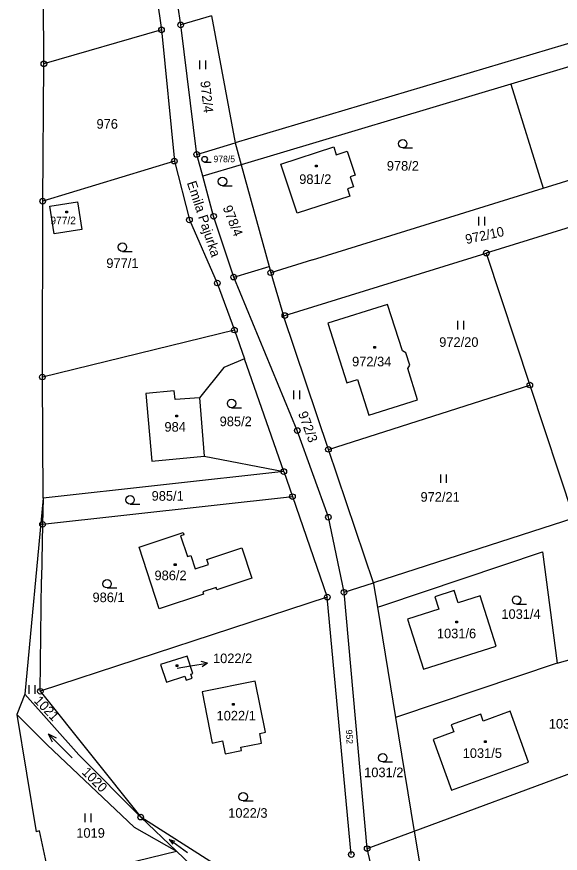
# Model space of a CAD drawing. Extents: x -468021 to -466942, y -1130484 to -1128584.
# Drawn here: x -467170.8 to -467074.6, y -1129387.9 to -1129239.8 of the extents above; entities that cross this region are included whole.
import ezdxf

# ---------------------------------------------------------------- set-up
doc = ezdxf.new("R2010")
doc.units = 0
doc.layers.add('DKM', color=7, linetype='Continuous')

msp = doc.modelspace()

# ---------------------------------------------------------------- linework, layer by layer
at = {"layer": 'DKM'}
for p, q in [((-467148.33, -1129219.55), (-467145.18, -1129242.09)), ((-467166.01, -1129248.11), (-467166.19, -1129224.44)), ((-467141.78, -1129241.21), (-467142.45, -1129236.44)), ((-467048.81, -1129237.23), (-467132.13, -1129262.11)), ((-467136.35, -1129239.61), (-467141.78, -1129241.21)), ((-467136.35, -1129239.61), (-467132.13, -1129262.11)), ((-467145.18, -1129242.09), (-467166.01, -1129248.11)), ((-467145.18, -1129242.09), (-467142.9, -1129265.33)), ((-467138.94, -1129264.14), (-467141.78, -1129241.21)), ((-467047.69, -1129241.07), (-467083.32, -1129251.71)), ((-467166.22, -1129272.43), (-467166.01, -1129248.11)), ((-467138.41, -1129249.04), (-467138.41, -1129247.54)), ((-467137.41, -1129247.54), (-467137.41, -1129249.04)), ((-467083.32, -1129251.71), (-467131.07, -1129265.96)), ((-467083.32, -1129251.71), (-467077.6, -1129270.12)), ((-467138.94, -1129264.14), (-467132.13, -1129262.11)), ((-467132.13, -1129262.11), (-467131.07, -1129265.96)), ((-467124.04, -1129265.86), (-467114.69, -1129262.77)), ((-467114.69, -1129262.77), (-467114.24, -1129264.19)), ((-467102.46, -1129262.99), (-467100.71, -1129262.99)), ((-467137.89, -1129268), (-467138.94, -1129264.14)), ((-467114.24, -1129264.19), (-467112.29, -1129263.55)), ((-467112.29, -1129263.55), (-467110.87, -1129267.83)), ((-467142.9, -1129265.33), (-467166.22, -1129272.43)), ((-467142.9, -1129265.33), (-467140.24, -1129275.75)), ((-467131.07, -1129265.96), (-467137.89, -1129268)), ((-467137.54, -1129265.49), (-467136.37, -1129265.49)), ((-467131.07, -1129265.96), (-467126.13, -1129284.01)), ((-467121.13, -1129274.57), (-467124.04, -1129265.86)), ((-467117.89, -1129266.06), (-467117.59, -1129266.06)), ((-467117.89, -1129266.36), (-467117.89, -1129266.06)), ((-467117.59, -1129266.06), (-467117.59, -1129266.36)), ((-467117.59, -1129266.36), (-467117.89, -1129266.36)), ((-467077.6, -1129270.12), (-467069.36, -1129267.56)), ((-467135.95, -1129275.1), (-467137.89, -1129268)), ((-467110.87, -1129267.83), (-467111.78, -1129268.12)), ((-467111.78, -1129268.12), (-467111.2, -1129269.88)), ((-467134.39, -1129269.68), (-467132.64, -1129269.68)), ((-467118.43, -1129282.79), (-467077.6, -1129270.12)), ((-467111.2, -1129269.88), (-467112.24, -1129270.23)), ((-467112.24, -1129270.23), (-467111.82, -1129271.51)), ((-467111.82, -1129271.51), (-467121.13, -1129274.57)), ((-467166.28, -1129303.56), (-467166.22, -1129272.43)), ((-467162.12, -1129274.18), (-467161.82, -1129274.18)), ((-467162.12, -1129274.48), (-467162.12, -1129274.18)), ((-467161.82, -1129274.48), (-467162.12, -1129274.48)), ((-467161.82, -1129274.18), (-467161.82, -1129274.48)), ((-467140.24, -1129275.75), (-467135.3, -1129286.92)), ((-467132.39, -1129285.86), (-467135.95, -1129275.1)), ((-467088.99, -1129276.7), (-467088.99, -1129275.2)), ((-467087.99, -1129275.2), (-467087.99, -1129276.7)), ((-467069.03, -1129275.85), (-467087.66, -1129281.62)), ((-467152.11, -1129281.31), (-467150.36, -1129281.31)), ((-467123.34, -1129292.67), (-467087.66, -1129281.62)), ((-467087.66, -1129281.62), (-467079.95, -1129304.98)), ((-467118.43, -1129282.79), (-467125.84, -1129285.08)), ((-467132.39, -1129285.86), (-467126.13, -1129284.01)), ((-467126.13, -1129284.01), (-467125.84, -1129285.08)), ((-467125.84, -1129285.08), (-467123.57, -1129292.74)), ((-467121.13, -1129313.03), (-467132.39, -1129285.86)), ((-467135.3, -1129286.92), (-467132.27, -1129295.24)), ((-467105.15, -1129290.73), (-467115.7, -1129294.04)), ((-467102.53, -1129298.94), (-467105.15, -1129290.73)), ((-467123.57, -1129292.74), (-467123.34, -1129292.67)), ((-467115.61, -1129316.37), (-467123.57, -1129292.74)), ((-467115.7, -1129294.04), (-467112.37, -1129304.59)), ((-467092.68, -1129295.12), (-467092.68, -1129293.62)), ((-467091.68, -1129293.62), (-467091.68, -1129295.12)), ((-467132.27, -1129295.24), (-467166.28, -1129303.56)), ((-467132.27, -1129295.24), (-467130.49, -1129300.34)), ((-467107.58, -1129298.14), (-467107.28, -1129298.14)), ((-467107.58, -1129298.44), (-467107.58, -1129298.14)), ((-467107.28, -1129298.44), (-467107.58, -1129298.44)), ((-467107.28, -1129298.14), (-467107.28, -1129298.44)), ((-467101.9, -1129299.25), (-467102.53, -1129298.94)), ((-467101.21, -1129301.44), (-467101.9, -1129299.25)), ((-467130.49, -1129300.34), (-467134.12, -1129301.86)), ((-467123.53, -1129320.29), (-467130.49, -1129300.34)), ((-467101.55, -1129302.05), (-467101.21, -1129301.44)), ((-467134.12, -1129301.86), (-467138.44, -1129307.25)), ((-467099.83, -1129307.62), (-467101.55, -1129302.05)), ((-467166.15, -1129325.02), (-467166.28, -1129303.56)), ((-467112.37, -1129304.59), (-467110.49, -1129304)), ((-467110.49, -1129304), (-467108.49, -1129310.3)), ((-467142.91, -1129306.01), (-467147.94, -1129306.45)), ((-467142.74, -1129307.54), (-467142.91, -1129306.01)), ((-467121.77, -1129307.47), (-467121.77, -1129305.97)), ((-467120.77, -1129305.97), (-467120.77, -1129307.47)), ((-467115.61, -1129316.37), (-467079.95, -1129304.98)), ((-467079.95, -1129304.98), (-467072.24, -1129328.35)), ((-467147.94, -1129306.45), (-467146.89, -1129318.46)), ((-467138.44, -1129307.25), (-467142.74, -1129307.54)), ((-467138.44, -1129307.25), (-467137.6, -1129317.57)), ((-467132.76, -1129308.99), (-467131.01, -1129308.99)), ((-467108.49, -1129310.3), (-467099.83, -1129307.62)), ((-467142.67, -1129310.31), (-467142.37, -1129310.31)), ((-467142.67, -1129310.61), (-467142.67, -1129310.31)), ((-467142.37, -1129310.31), (-467142.37, -1129310.61)), ((-467142.37, -1129310.61), (-467142.67, -1129310.61)), ((-467115.63, -1129328.38), (-467121.13, -1129313.03)), ((-467107.66, -1129340.01), (-467115.61, -1129316.37)), ((-467146.89, -1129318.46), (-467137.6, -1129317.57)), ((-467137.6, -1129317.57), (-467123.53, -1129320.29)), ((-467123.53, -1129320.29), (-467166.15, -1129325.02)), ((-467123.53, -1129320.29), (-467121.99, -1129324.74)), ((-467095.74, -1129322.32), (-467095.74, -1129320.82)), ((-467094.74, -1129320.82), (-467094.74, -1129322.32)), ((-467166.15, -1129325.02), (-467169.37, -1129359.74)), ((-467166.24, -1129329.64), (-467121.99, -1129324.74)), ((-467166.15, -1129325.02), (-467166.24, -1129329.64)), ((-467121.99, -1129324.74), (-467115.82, -1129342.52)), ((-467150.75, -1129326.06), (-467149, -1129326.06)), ((-467166.24, -1129329.64), (-467166.43, -1129339.33)), ((-467112.85, -1129341.68), (-467115.63, -1129328.38)), ((-467072.17, -1129328.56), (-467107.66, -1129340.01)), ((-467149.16, -1129333.66), (-467141.34, -1129331.08)), ((-467141.34, -1129331.08), (-467141.21, -1129331.5)), ((-467141.21, -1129331.5), (-467141.81, -1129331.7)), ((-467141.81, -1129331.7), (-467140.59, -1129335.34)), ((-467145.58, -1129344.58), (-467149.16, -1129333.66)), ((-467137.15, -1129335.85), (-467130.96, -1129333.8)), ((-467130.96, -1129333.8), (-467129.2, -1129339.18)), ((-467140.59, -1129335.34), (-467139.99, -1129335.16)), ((-467139.99, -1129335.16), (-467139.2, -1129337.54)), ((-467106, -1129344.02), (-467077.72, -1129334.5)), ((-467077.72, -1129334.5), (-467075.11, -1129354.21)), ((-467142.91, -1129336.62), (-467142.61, -1129336.62)), ((-467142.91, -1129336.92), (-467142.91, -1129336.62)), ((-467142.61, -1129336.92), (-467142.91, -1129336.92)), ((-467142.61, -1129336.62), (-467142.61, -1129336.92)), ((-467139.2, -1129337.54), (-467136.85, -1129336.75)), ((-467136.85, -1129336.75), (-467137.15, -1129335.85)), ((-467166.64, -1129359.2), (-467166.43, -1129339.33)), ((-467129.2, -1129339.18), (-467135.39, -1129341.22)), ((-467112.85, -1129341.68), (-467107.66, -1129340.01)), ((-467107.66, -1129340.01), (-467107.61, -1129340.15)), ((-467107.61, -1129340.15), (-467106.92, -1129344.33)), ((-467154.82, -1129340.91), (-467153.07, -1129340.91)), ((-467135.52, -1129340.81), (-467137.88, -1129341.58)), ((-467137.88, -1129341.58), (-467137.74, -1129341.99)), ((-467135.39, -1129341.22), (-467135.52, -1129340.81)), ((-467093.33, -1129341.35), (-467096.79, -1129342.45)), ((-467092.63, -1129343.55), (-467093.33, -1129341.35)), ((-467115.82, -1129342.52), (-467166.64, -1129359.2)), ((-467137.74, -1129341.99), (-467145.58, -1129344.58)), ((-467111.57, -1129388.11), (-467115.82, -1129342.52)), ((-467108.76, -1129387.06), (-467112.85, -1129341.68)), ((-467096.79, -1129342.45), (-467096.08, -1129344.65)), ((-467088.73, -1129342.31), (-467092.63, -1129343.55)), ((-467085.89, -1129351.23), (-467088.73, -1129342.31)), ((-467106.92, -1129344.33), (-467106, -1129344.02)), ((-467106.92, -1129344.33), (-467103.72, -1129363.86)), ((-467082.29, -1129343.79), (-467080.54, -1129343.79)), ((-467096.08, -1129344.65), (-467101.61, -1129346.41)), ((-467101.61, -1129346.41), (-467098.8, -1129355.31)), ((-467093.08, -1129346.8), (-467092.78, -1129346.8)), ((-467093.08, -1129347.1), (-467093.08, -1129346.8)), ((-467092.78, -1129347.1), (-467093.08, -1129347.1)), ((-467092.78, -1129346.8), (-467092.78, -1129347.1)), ((-467098.8, -1129355.31), (-467085.89, -1129351.23)), ((-467140.66, -1129352.99), (-467145.36, -1129354.47)), ((-467139.62, -1129356.04), (-467140.66, -1129352.99)), ((-467075.11, -1129354.21), (-467068.66, -1129352.46)), ((-467145.36, -1129354.47), (-467144.31, -1129357.61)), ((-467142.58, -1129354.53), (-467142.28, -1129354.53)), ((-467142.58, -1129354.83), (-467142.58, -1129354.53)), ((-467142.28, -1129354.83), (-467142.58, -1129354.83)), ((-467142.41, -1129355.12), (-467140.02, -1129354.72)), ((-467142.28, -1129354.53), (-467142.28, -1129354.83)), ((-467140.02, -1129354.72), (-467137.06, -1129354.22)), ((-467137.06, -1129354.22), (-467138.13, -1129353.9)), ((-467137.06, -1129354.22), (-467137.96, -1129354.88)), ((-467075.11, -1129354.21), (-467103.38, -1129363.75)), ((-467140, -1129356.17), (-467139.62, -1129356.04)), ((-467139.76, -1129356.89), (-467140, -1129356.17)), ((-467144.31, -1129357.61), (-467141.06, -1129356.52)), ((-467141.06, -1129356.52), (-467140.82, -1129357.24)), ((-467140.82, -1129357.24), (-467139.76, -1129356.89)), ((-467128.61, -1129357.39), (-467137.97, -1129359.3)), ((-467126.76, -1129366.44), (-467128.61, -1129357.39)), ((-467168.64, -1129359.63), (-467168.64, -1129358.13)), ((-467167.64, -1129358.13), (-467167.64, -1129359.63)), ((-467166.64, -1129359.2), (-467148.86, -1129381.48)), ((-467137.97, -1129359.3), (-467136.19, -1129368.38)), ((-467169.37, -1129359.74), (-467170.82, -1129363.32)), ((-467169.37, -1129359.74), (-467159.84, -1129370.48)), ((-467132.62, -1129361.36), (-467132.32, -1129361.36)), ((-467132.62, -1129361.66), (-467132.62, -1129361.36)), ((-467132.32, -1129361.66), (-467132.62, -1129361.66)), ((-467132.32, -1129361.36), (-467132.32, -1129361.66)), ((-467170.82, -1129363.32), (-467165.45, -1129368.67)), ((-467170.82, -1129363.32), (-467167.38, -1129384.06)), ((-467103.38, -1129363.75), (-467103.72, -1129363.86)), ((-467103.72, -1129363.86), (-467100.47, -1129383.69)), ((-467088.64, -1129363.24), (-467093.89, -1129365.15)), ((-467088.19, -1129364.47), (-467088.64, -1129363.24)), ((-467083.46, -1129362.75), (-467088.19, -1129364.47)), ((-467080.17, -1129371.77), (-467083.46, -1129362.75)), ((-467093.89, -1129365.15), (-467093.43, -1129366.39)), ((-467161.02, -1129371), (-467165.26, -1129366.76)), ((-467165.26, -1129366.76), (-467164.55, -1129368.17)), ((-467165.26, -1129366.76), (-467163.85, -1129367.47)), ((-467127.77, -1129366.68), (-467126.76, -1129366.44)), ((-467127.5, -1129368.39), (-467127.77, -1129366.68)), ((-467093.43, -1129366.39), (-467097.05, -1129367.71)), ((-467136.19, -1129368.38), (-467134.36, -1129368)), ((-467134.36, -1129368), (-467133.89, -1129370.3)), ((-467097.05, -1129367.71), (-467093.83, -1129376.73)), ((-467088, -1129367.99), (-467087.7, -1129367.99)), ((-467088, -1129368.29), (-467088, -1129367.99)), ((-467087.7, -1129368.29), (-467088, -1129368.29)), ((-467087.7, -1129367.99), (-467087.7, -1129368.29)), ((-467165.45, -1129368.67), (-467150.03, -1129383.28)), ((-467133.89, -1129370.3), (-467131.03, -1129369.71)), ((-467131.16, -1129369.12), (-467127.5, -1129368.39)), ((-467131.03, -1129369.71), (-467131.16, -1129369.12)), ((-467159.84, -1129370.48), (-467148.86, -1129381.48)), ((-467100.42, -1129383.97), (-467062.59, -1129369.93)), ((-467106, -1129371.71), (-467104.25, -1129371.71)), ((-467093.83, -1129376.73), (-467080.17, -1129371.77)), ((-467130.72, -1129378.62), (-467128.97, -1129378.62)), ((-467158.68, -1129382.36), (-467158.68, -1129380.86)), ((-467157.68, -1129380.86), (-467157.68, -1129382.36)), ((-467148.86, -1129381.48), (-467142.53, -1129387.51)), ((-467135.99, -1129389.69), (-467148.86, -1129381.48)), ((-467166.79, -1129383.93), (-467167.38, -1129384.06)), ((-467164.86, -1129392.93), (-467166.79, -1129383.93)), ((-467150.03, -1129383.28), (-467142.53, -1129387.51)), ((-467108.76, -1129387.06), (-467100.42, -1129383.97)), ((-467100.47, -1129383.69), (-467100.42, -1129383.97)), ((-467100.42, -1129383.97), (-467093.45, -1129426.61)), ((-467140.56, -1129387.79), (-467143.82, -1129385.43)), ((-467143.82, -1129385.43), (-467143.2, -1129386.29)), ((-467143.82, -1129385.43), (-467142.81, -1129385.75)), ((-467156.59, -1129390.92), (-467142.53, -1129387.51)), ((-467142.53, -1129387.51), (-467137.61, -1129392.19)), ((-467098.83, -1129428.25), (-467108.76, -1129387.06))]:
    msp.add_line(p, q, dxfattribs=at)
msp.add_lwpolyline([(-467164.17, -1129278.2), (-467164.96, -1129273.3), (-467160.05, -1129272.51), (-467159.27, -1129277.42), (-467164.17, -1129278.2)], dxfattribs=at)
for centre, radius in [((-467141.78, -1129241.21), 0.5), ((-467145.18, -1129242.09), 0.5), ((-467145.18, -1129242.09), 0.01), ((-467141.78, -1129241.21), 0.01), ((-467166.01, -1129248.11), 0.5), ((-467166.01, -1129248.11), 0.01), ((-467102.46, -1129262.24), 0.75), ((-467138.94, -1129264.14), 0.5), ((-467138.94, -1129264.14), 0.01), ((-467137.54, -1129264.99), 0.503), ((-467142.9, -1129265.33), 0.5), ((-467142.9, -1129265.33), 0.01), ((-467134.39, -1129268.93), 0.75), ((-467166.22, -1129272.43), 0.5), ((-467166.22, -1129272.43), 0.01), ((-467135.95, -1129275.1), 0.5), ((-467140.24, -1129275.75), 0.5), ((-467140.24, -1129275.75), 0.01), ((-467135.95, -1129275.1), 0.01), ((-467152.11, -1129280.56), 0.75), ((-467087.66, -1129281.62), 0.5), ((-467087.66, -1129281.62), 0.01), ((-467132.39, -1129285.86), 0.5), ((-467125.84, -1129285.08), 0.5), ((-467125.84, -1129285.08), 0.01), ((-467135.3, -1129286.92), 0.5), ((-467132.39, -1129285.86), 0.01), ((-467135.3, -1129286.92), 0.01), ((-467123.34, -1129292.67), 0.5), ((-467123.34, -1129292.67), 0.01), ((-467132.27, -1129295.24), 0.5), ((-467132.27, -1129295.24), 0.01), ((-467166.28, -1129303.56), 0.5), ((-467166.28, -1129303.56), 0.01), ((-467079.95, -1129304.98), 0.5), ((-467079.95, -1129304.98), 0.01), ((-467132.76, -1129308.24), 0.75), ((-467121.13, -1129313.03), 0.5), ((-467121.13, -1129313.03), 0.01), ((-467115.61, -1129316.37), 0.5), ((-467115.61, -1129316.37), 0.01), ((-467123.53, -1129320.29), 0.5), ((-467123.53, -1129320.29), 0.01), ((-467150.75, -1129325.31), 0.75), ((-467121.99, -1129324.74), 0.5), ((-467121.99, -1129324.74), 0.01), ((-467115.63, -1129328.38), 0.5), ((-467166.24, -1129329.64), 0.5), ((-467166.24, -1129329.64), 0.01), ((-467115.63, -1129328.38), 0.01), ((-467154.82, -1129340.16), 0.75), ((-467112.85, -1129341.68), 0.5), ((-467112.85, -1129341.68), 0.01), ((-467115.82, -1129342.52), 0.5), ((-467115.82, -1129342.52), 0.01), ((-467082.29, -1129343.04), 0.75), ((-467166.64, -1129359.2), 0.5), ((-467166.64, -1129359.2), 0.01), ((-467106, -1129370.96), 0.75), ((-467130.72, -1129377.87), 0.75), ((-467148.86, -1129381.48), 0.5), ((-467148.86, -1129381.48), 0.01), ((-467108.76, -1129387.06), 0.5), ((-467108.76, -1129387.06), 0.01), ((-467111.57, -1129388.11), 0.5)]:
    msp.add_circle(centre, radius, dxfattribs=at)

# ---------------------------------------------------------------- texts
for s, height, rotation, p in [('972/4', 1.7, 276.2513, (-467138.3, -1129251.2)), ('Emila Pajurka', 1.7, 288.3892, (-467140.71, -1129269.17)), ('978/4', 1.7, 291.5713, (-467134.38, -1129273.55)), ('972/10', 1.7, 12.3516, (-467091.18, -1129280.04)), ('972/3', 1.7, 290.2437, (-467121.02, -1129309.99)), ('1021', 1.7, 313.8147, (-467167.88, -1129360.99)), ('952', 1.14, 273.2822, (-467112.54, -1129366.03)), ('1020', 1.7, 315, (-467159.4, -1129373.66))]:
    msp.add_text(s, height=height, rotation=rotation, dxfattribs=at).set_placement(p)
for s, height, p in [('976', 1.7, (-467156.69, -1129259.59)), ('978/5', 1.14, (-467135.97, -1129265.52)), ('978/2', 1.7, (-467105.28, -1129267.02)), ('981/2', 1.7, (-467120.79, -1129269.37)), ('977/2', 1.35, (-467164.86, -1129276.52)), ('977/1', 1.7, (-467154.95, -1129284.25)), ('972/20', 1.7, (-467096, -1129298.22)), ('972/34', 1.7, (-467111.43, -1129301.67)), ('985/2', 1.7, (-467134.88, -1129312.26)), ('984', 1.7, (-467144.66, -1129313.23)), ('985/1', 1.7, (-467146.93, -1129325.46)), ('972/21', 1.7, (-467099.31, -1129325.64)), ('986/2', 1.7, (-467146.42, -1129339.53)), ('986/1', 1.7, (-467157.4, -1129343.42)), ('1031/4', 1.7, (-467084.99, -1129346.38)), ('1031/6', 1.7, (-467096.41, -1129349.81)), ('1022/2', 1.7, (-467136.06, -1129354.22)), ('1022/2', 0.1, (-467142.41, -1129355.12)), ('1022/1', 1.7, (-467135.43, -1129364.37)), ('1031/3', 1.7, (-467076.59, -1129365.8)), ('1031/5', 1.7, (-467091.84, -1129371)), ('1031/2', 1.7, (-467109.29, -1129374.41)), ('1022/3', 1.7, (-467133.36, -1129381.6)), ('1019', 1.7, (-467160.27, -1129385.14))]:
    msp.add_text(s, height=height, dxfattribs=at).set_placement(p)

doc.saveas('drawing.dxf')
